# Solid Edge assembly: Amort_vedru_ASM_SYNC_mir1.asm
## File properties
Author: KULL
Template: Iso Metric Assembly.asm
Last saved by: KULL
Revision: 2
Application: Solid Edge
Username: KULL
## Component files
Amort_sync.par
vedru__sync_mir1.par
Amort_vedru_ASM_SYNC.asm
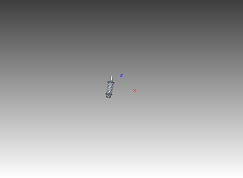
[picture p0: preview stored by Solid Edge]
